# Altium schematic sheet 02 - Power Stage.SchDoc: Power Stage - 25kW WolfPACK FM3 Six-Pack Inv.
size 431 x 279 mm; Date: 01/2024; DocumentNumber: CRD25DA12N-FMC; Revision: 1.2; SheetNumber: 2; SheetTotal: 8; SheetSize: B
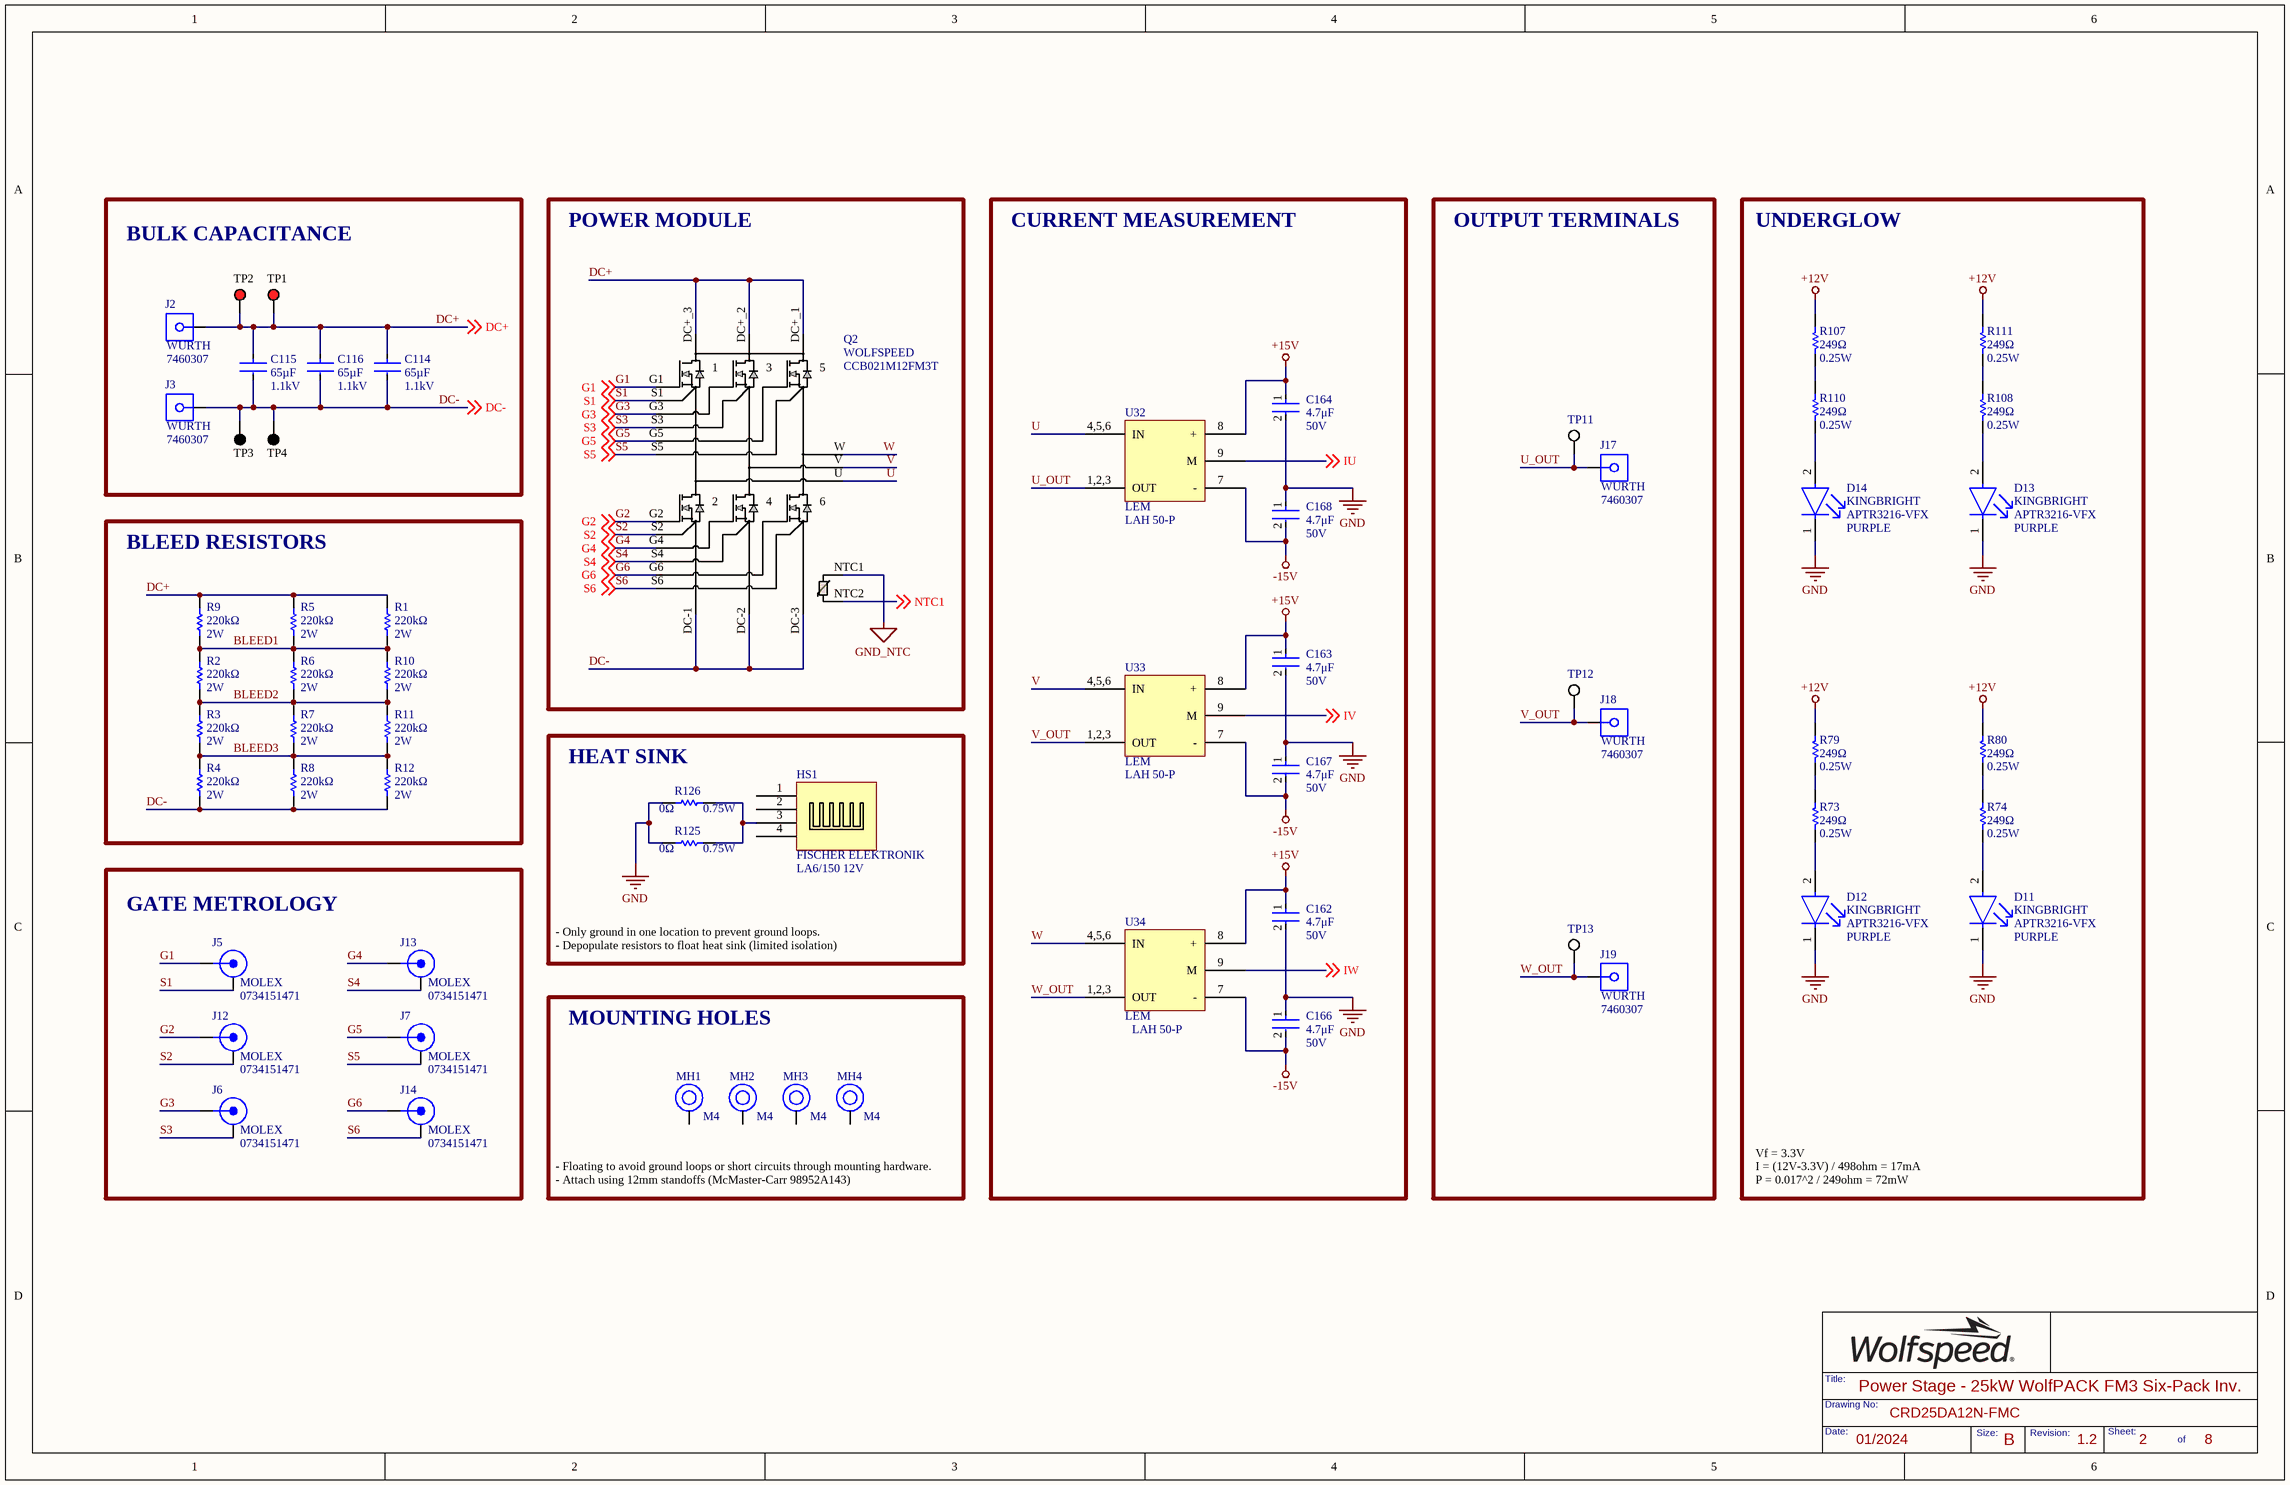
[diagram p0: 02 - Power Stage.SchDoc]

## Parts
C114  Voltage: 1.1kV  Capacitance: 65µF  [C4AQQEW5650A3BJ]  (hidden comment: C4AQQEW5650A3BJ)
C115  Voltage: 1.1kV  Capacitance: 65µF  [C4AQQEW5650A3BJ]  (hidden comment: C4AQQEW5650A3BJ)
C116  Voltage: 1.1kV  Capacitance: 65µF  [C4AQQEW5650A3BJ]  (hidden comment: C4AQQEW5650A3BJ)
C162  Voltage Rating: 50V  Capacitance: 4.7μF  [FP-CL31-IPC_C]  (hidden comment: CL31B475KBHNFNE)
C163  Voltage Rating: 50V  Capacitance: 4.7μF  [FP-CL31-IPC_C]  (hidden comment: CL31B475KBHNFNE)
C164  Voltage Rating: 50V  Capacitance: 4.7μF  [FP-CL31-IPC_C]  (hidden comment: CL31B475KBHNFNE)
C166  Voltage Rating: 50V  Capacitance: 4.7μF  [FP-CL31-IPC_C]  (hidden comment: CL31B475KBHNFNE)
C167  Voltage Rating: 50V  Capacitance: 4.7μF  [FP-CL31-IPC_C]  (hidden comment: CL31B475KBHNFNE)
C168  Voltage Rating: 50V  Capacitance: 4.7μF  [FP-CL31-IPC_C]  (hidden comment: CL31B475KBHNFNE)
D11  Manufacturer Print: KINGBRIGHT  Color: PURPLE  [FP-APTR3216SECK-MFG]  (hidden comment: APTR3216-VFX)
D12  Manufacturer: KINGBRIGHT  Color: PURPLE  [FP-APTR3216SECK-MFG]  (hidden comment: APTR3216-VFX)
D13  Manufacturer Print: KINGBRIGHT  Color: PURPLE  [FP-APTR3216SECK-MFG]  (hidden comment: APTR3216-VFX)
D14  Manufacturer Print: KINGBRIGHT  Color: PURPLE  [FP-APTR3216SECK-MFG]  (hidden comment: APTR3216-VFX)
HS1  LA6/150 12V  Manufacturer: FISCHER ELEKTRONIK  [LA 6 150 12]
J2  Manufacturer Print: WURTH  [7460307]  (hidden comment: 7460307)
J3  Manufacturer Print: WURTH  [7460307]  (hidden comment: 7460307)
J5  0734151471  Manufacturer Print: MOLEX  [FP-73415-1471-MFG]
J6  0734151471  Manufacturer Print: MOLEX  [FP-73415-1471-MFG]
J7  0734151471  Manufacturer Print: MOLEX  [FP-73415-1471-MFG]
J12  0734151471  Manufacturer Print: MOLEX  [FP-73415-1471-MFG]
J13  0734151471  Manufacturer Print: MOLEX  [FP-73415-1471-MFG]
J14  0734151471  Manufacturer Print: MOLEX  [FP-73415-1471-MFG]
J17  Manufacturer Print: WURTH  [7460307]  (hidden comment: 7460307)
J18  Manufacturer Print: WURTH  [7460307]  (hidden comment: 7460307)
J19  Manufacturer Print: WURTH  [7460307]  (hidden comment: 7460307)
MH1  Size: M4  [MH_M4_P]  (hidden comment: MH_M4_P)
MH2  Size: M4  [MH_M4_P]  (hidden comment: MH_M4_P)
MH3  Size: M4  [MH_M4_P]  (hidden comment: MH_M4_P)
MH4  Size: M4  [MH_M4_P]  (hidden comment: MH_M4_P)
Q2  CCB021M12FM3T  Manufacturer Print: WOLFSPEED  [FM3_SIX-PACK_3PHASE_CRW]
R1  Power Rating: 2W  Resistance: 220kΩ  [FP-CRGP2512-IPC_C]  (hidden comment: CRGP2512F220K)
R2  Power Rating: 2W  Resistance: 220kΩ  [FP-CRGP2512-IPC_C]  (hidden comment: CRGP2512F220K)
R3  Power Rating: 2W  Resistance: 220kΩ  [FP-CRGP2512-IPC_C]  (hidden comment: CRGP2512F220K)
R4  Power Rating: 2W  Resistance: 220kΩ  [FP-CRGP2512-IPC_C]  (hidden comment: CRGP2512F220K)
R5  Power Rating: 2W  Resistance: 220kΩ  [FP-CRGP2512-IPC_C]  (hidden comment: CRGP2512F220K)
R6  Power Rating: 2W  Resistance: 220kΩ  [FP-CRGP2512-IPC_C]  (hidden comment: CRGP2512F220K)
R7  Power Rating: 2W  Resistance: 220kΩ  [FP-CRGP2512-IPC_C]  (hidden comment: CRGP2512F220K)
R8  Power Rating: 2W  Resistance: 220kΩ  [FP-CRGP2512-IPC_C]  (hidden comment: CRGP2512F220K)
R9  Power Rating: 2W  Resistance: 220kΩ  [FP-CRGP2512-IPC_C]  (hidden comment: CRGP2512F220K)
R10  Power Rating: 2W  Resistance: 220kΩ  [FP-CRGP2512-IPC_C]  (hidden comment: CRGP2512F220K)
R11  Power Rating: 2W  Resistance: 220kΩ  [FP-CRGP2512-IPC_C]  (hidden comment: CRGP2512F220K)
R12  Power Rating: 2W  Resistance: 220kΩ  [FP-CRGP2512-IPC_C]  (hidden comment: CRGP2512F220K)
R73  Resistance: 249Ω  Power Rating: 0.25W  [FP-MCR18-IPC_A]  (hidden comment: RC1206FR-07249RL)
R74  Resistance: 249Ω  Power Rating: 0.25W  [FP-MCR18-IPC_A]  (hidden comment: RC1206FR-07249RL)
R79  Resistance: 249Ω  Power Rating: 0.25W  [FP-MCR18-IPC_A]  (hidden comment: RC1206FR-07249RL)
R80  Resistance: 249Ω  Power Rating: 0.25W  [FP-MCR18-IPC_A]  (hidden comment: RC1206FR-07249RL)
R107  Resistance: 249Ω  Power Rating: 0.25W  [FP-MCR18-IPC_A]  (hidden comment: RC1206FR-07249RL)
R108  Resistance: 249Ω  Power Rating: 0.25W  [FP-MCR18-IPC_A]  (hidden comment: RC1206FR-07249RL)
R110  Resistance: 249Ω  Power Rating: 0.25W  [FP-MCR18-IPC_A]  (hidden comment: RC1206FR-07249RL)
R111  Resistance: 249Ω  Power Rating: 0.25W  [FP-MCR18-IPC_A]  (hidden comment: RC1206FR-07249RL)
R125  value 0Ω  Power Rating: 0.75W  [RESC3125X70X40NL20T20]  (hidden comment: CRCW12100000Z0EAHP)
R126  value 0Ω  Power Rating: 0.75W  [RESC3125X70X40NL20T20]  (hidden comment: CRCW12100000Z0EAHP)
TP1  5010  [KSTN-5010_V]  (value not drawn)
TP2  5010  [KSTN-5010_V]  (value not drawn)
TP3  5011  [KSTN-5011_V]  (value not drawn)
TP4  5011  [KSTN-5011_V]  (value not drawn)
TP11  5012  [KSTN-5012_V]  (value not drawn)
TP12  5012  [KSTN-5012_V]  (value not drawn)
TP13  5012  [KSTN-5012_V]  (value not drawn)
U32  LAH 50-P  Manufacturer Print: LEM  [LAH 50-P]
U33  LAH 50-P  Manufacturer Print: LEM  [LAH 50-P]
U34  LAH 50-P  Manufacturer Print: LEM  [LAH 50-P]

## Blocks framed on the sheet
BULK CAPACITANCE: C114-C116 J2 J3 TP1-TP4
POWER MODULE: Q2
CURRENT MEASUREMENT: C162-C164 C166-C168 U32-U34
OUTPUT TERMINALS: J17-J19 TP11-TP13
UNDERGLOW: D11-D14 R73 R74 R79 R80 R107 R108 R110 R111
BLEED RESISTORS: R1-R12
HEAT SINK: HS1 R125 R126
GATE METROLOGY: J5-J7 J12-J14
MOUNTING HOLES: MH1-MH4

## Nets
+12V: R79.1 R80.1 R107.1 R111.1
+15V: C162.1 C163.1 C164.1 U32.8(+) U33.8(+) U34.8(+)
-15V: C166.2 C167.2 C168.2 U32.7(-) U33.7(-) U34.7(-)
GND: C162.2 C163.2 C164.2 C166.1 C167.1 C168.1 D11.1(C) D12.1(C) D13.1(C) D14.1(C) R125.1 R126.1
GND_NTC: Q2.NTC1
BLEED1: R1.1 R2.2 R5.1 R6.2 R9.1 R10.2
BLEED2: R2.1 R3.2 R6.1 R7.2 R10.1 R11.2
BLEED3: R3.1 R4.2 R7.1 R8.2 R11.1 R12.2
DC+: C114.1,2(+) C115.1,2(+) C116.1,2(+) J2.1,2,3,4,5,6,7,8 Q2.DC+_1 Q2.DC+_2 Q2.DC+_3 R1.2 R5.2 R9.2 TP1.1 TP2.1 ; off-sheet DC+
DC-: C114.3,4 C115.3,4 C116.3,4 J3.1,2,3,4,5,6,7,8 Q2.DC-1 Q2.DC-2 Q2.DC-3 R4.1 R8.1 R12.1 TP3.1 TP4.1 ; off-sheet DC-
G1: J5.1(CENTER) Q2.G1 ; off-sheet G1
G2: J12.1(CENTER) Q2.G2 ; off-sheet G2
G3: J6.1(CENTER) Q2.G3 ; off-sheet G3
G4: J13.1(CENTER) Q2.G4 ; off-sheet G4
G5: J7.1(CENTER) Q2.G5 ; off-sheet G5
G6: J14.1(CENTER) Q2.G6 ; off-sheet G6
IU: U32.9(M) ; off-sheet IU
IV: U33.9(M) ; off-sheet IV
IW: U34.9(M) ; off-sheet IW
NTC1: Q2.NTC2 ; off-sheet NTC1
S1: J5.2,3,4,5(SHIELD) Q2.S1 ; off-sheet S1
S2: J12.2,3,4,5(SHIELD) Q2.S2 ; off-sheet S2
S3: J6.2,3,4,5(SHIELD) Q2.S3 ; off-sheet S3
S4: J13.2,3,4,5(SHIELD) Q2.S4 ; off-sheet S4
S5: J7.2,3,4,5(SHIELD) Q2.S5 ; off-sheet S5
S6: J14.2,3,4,5(SHIELD) Q2.S6 ; off-sheet S6
U: Q2.U U32.4,5,6(IN)
U_OUT: J17.1,2,3,4,5,6,7,8 TP11.1 U32.1,2,3(OUT)
V: Q2.V U33.4,5,6(IN)
V_OUT: J18.1,2,3,4,5,6,7,8 TP12.1 U33.1,2,3(OUT)
W: Q2.W U34.4,5,6(IN)
W_OUT: J19.1,2,3,4,5,6,7,8 TP13.1 U34.1,2,3(OUT)
NetD11_2: D11.2(A) R74.2
NetD12_2: D12.2(A) R73.2
NetD13_2: D13.2(A) R108.2
NetD14_2: D14.2(A) R110.2
NetHS1_3: HS1.3 R125.2 R126.2
NetR73_1: R73.1 R79.2
NetR74_1: R74.1 R80.2
NetR107_2: R107.2 R110.1
NetR108_1: R108.1 R111.2

Not connected (* = marked no-connect by the designer): HS1 1 2 4; MH1 1; MH2 1; MH3 1; MH4 1

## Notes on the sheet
- - Only ground in one location to prevent ground loops.
  - Depopulate resistors to float heat sink (limited isolation)
- - Floating to avoid ground loops or short circuits through mounting hardware.
  - Attach using 12mm standoffs (McMaster-Carr 98952A143)
- Vf = 3.3V
  I = (12V-3.3V) / 498ohm = 17mA
  P = 0.017^2 / 249ohm = 72mW

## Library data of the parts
C114-C116 = C4AQQEW5650A3BJ: CAP FILM 65UF 5% 1.1KVDC RAD; Manufacturer: KEMET; Value: 65µF
C162-C164 C166-C168 = CMP-13271-001123-1: CAP CER 4.7UF 50V X7R 1206; Manufacturer: SAMSUNG; Tolerance: 10%; Value: 4.7μF
D11-D14 = APTR3216-VFX: LED PURPLE CLEAR 1206 SMD
HS1 = LA 6 150 12: HEATSINK EXTRUSION 150MM; Natural Thermal Resistance: 0.175°C/W; Power Consumption: 2.9W
J2 J3 J17-J19 = 7460307: TERM REDCUBE M4 8PIN PCB; Manufacturer: WURTH ELEKTRONIK; Current Rating: 80A; Number of Contacts: 8; Insulation: Non-Insulated
J5-J7 J12-J14 = 0734151471: CONN MMCX JACK STR 50 OHM PCB; Manufacturer Part Number: 73415-1471; Body Material: Brass; Body Plating: Gold; Impedance: 50R; Connector Type: PCB,MMCX,Coaxial; Max Frequency: 6GHz; Gender: Female
MH1-MH4 = MH_M4_P: HEX STANDOFF M4 ALUMINUM 51MM F-F; Manufacturer: MCMASTER-CARR; Manufacturer Part Number: 95947A552
Q2 = CCB021M12FM3: SIC 6N-CH 1200V 30A MODULE; Mfr_Name: Cree Wolfspeed; Type: DEV
R1-R12 = CMP-03211-002966-1: RES 220K OHM 1% 2W 2512; Manufacturer: TE; Value: 220kΩ; Temperature Coefficient: ±100ppm/°C; Tolerance: 0.01; Voltage Rating: 500V
R73 R74 R79 R80 R107 R108 R110 R111 = RC1206FR-07249RL: RES 249 OHM 1% 1/4W 1206; Manufacturer: YAGEO; Voltage Rating: 200V; Temperature Coefficient: 100ppm/°C; Max Power Dissipation: 250mW; Value: 249Ω
R125 R126 = CRCW12100000Z0EAHP: RES SMD 0 OHM JUMPER 3/4W 1210; Manufacturer: VISHAY DALE; Max Power Dissipation: 750mW
TP1 TP2 = CMP-1672-00002-4: PC TEST POINT MULTIPURPOSE RED; Manufacturer: KEYSTONE
TP3 TP4 = CMP-1672-00003-4: PC TEST POINT MULTIPURPOSE BLACK; Manufacturer: KEYSTONE
TP11-TP13 = CMP-1672-00004-4: PC TEST POINT MULTIPURPOSE WHITE; Manufacturer: KEYSTONE
U32-U34 = LAH 50-P: SENSOR CURRENT HALL 50A AC/DC; Frequency: 200kHz; Number of Channels: 1; Response Time: 0.5us; Max Supply Current: 35mA; Polarity: Bidirectional; Linearity: 0.15%; Accuracy: 0.25%; Operating Supply Voltage: 15V; Secondary Current: 25mA; Overall Height: 21mm; Overall Depth: 14.93mm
